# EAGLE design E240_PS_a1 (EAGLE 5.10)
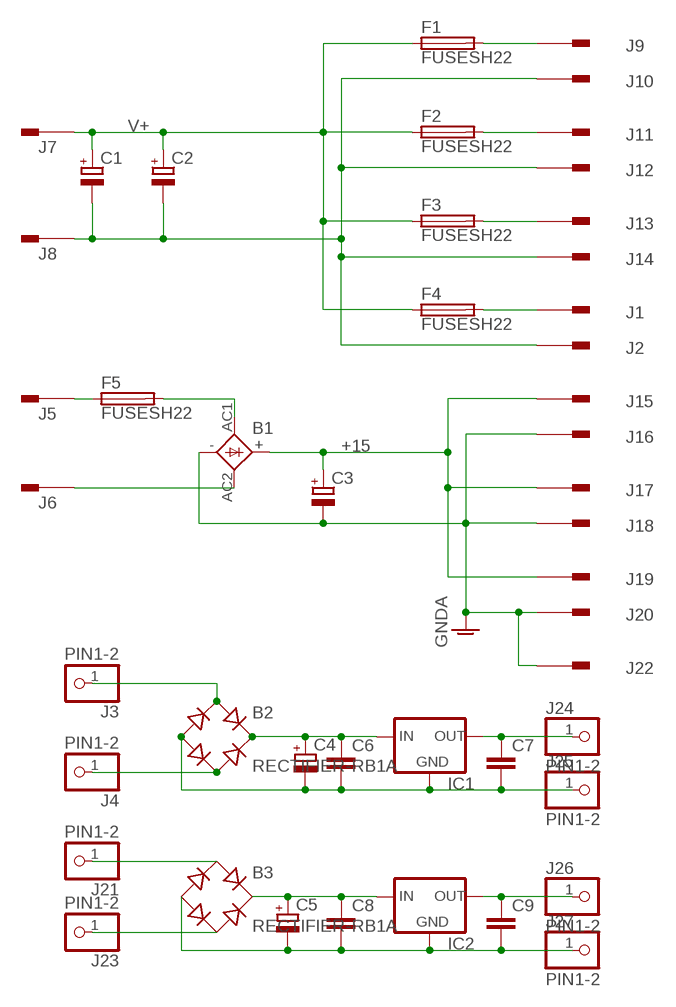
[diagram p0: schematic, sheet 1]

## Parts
B1  KBU  [KBU]
B2  RECTIFIER-RB1A  [RB1A]
B3  RECTIFIER-RB1A  [RB1A]
C1  CPOL-EUE10-35  [EB35D]
C2  CPOL-EUE10-35  [EB35D]
C3  CPOL-EUE10-22.5  [EB22,5D]
C4  CPOL-EUE5-10.5  [E5-10,5]
C5  CPOL-EUE5-10.5  [E5-10,5]
C6  C-EU050-035X075  [C050-035X075]
C7  C-EU050-035X075  [C050-035X075]
C8  C-EU050-035X075  [C050-035X075]
C9  C-EU050-035X075  [C050-035X075]
F1  FUSESH22  [SH22]
F2  FUSESH22  [SH22]
F3  FUSESH22  [SH22]
F4  FUSESH22  [SH22]
F5  FUSESH22  [SH22]
IC1  78XXS  [78XXS]
IC2  78XXS  [78XXS]
J1  PIN262409-1  [62409-1]
J2  PIN262409-1  [62409-1]
J3  PIN1-2  PINHD-1X1-RB  [1X01-B]
J4  PIN1-2  PINHD-1X1-RB  [1X01-B]
J5  PIN262409-1  [62409-1]
J6  PIN262409-1  [62409-1]
J7  PIN262409-1  [62409-1]
J8  PIN262409-1  [62409-1]
J9  PIN262409-1  [62409-1]
J10  PIN262409-1  [62409-1]
J11  PIN262409-1  [62409-1]
J12  PIN262409-1  [62409-1]
J13  PIN262409-1  [62409-1]
J14  PIN262409-1  [62409-1]
J15  PIN262409-1  [62409-1]
J16  PIN262409-1  [62409-1]
J17  PIN262409-1  [62409-1]
J18  PIN262409-1  [62409-1]
J19  PIN262409-1  [62409-1]
J20  PIN262409-1  [62409-1]
J21  PIN1-2  PINHD-1X1-RB  [1X01-B]
J22  PIN262409-1  [62409-1]
J23  PIN1-2  PINHD-1X1-RB  [1X01-B]
J24  PIN1-2  PINHD-1X1-RB  [1X01-B]
J25  PIN1-2  PINHD-1X1-RB  [1X01-B]
J26  PIN1-2  PINHD-1X1-RB  [1X01-B]
J27  PIN1-2  PINHD-1X1-RB  [1X01-B]

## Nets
+15 [PWR]: B1.+ C3.+ J15.A1 J17.A1 J19.A1
GND: B1.- C3.- J16.A1 J18.A1 J20.A1 J22.A1 ; supply symbol labelled GNDA
GNDP: C1.- C2.- J2.A1 J8.A1 J10.A1 J12.A1 J14.A1
N$1: C7.1 IC1.OUT J24.1
N$2: F1.2 J9.A1
N$3: F2.2 J11.A1
N$4 [PWR]: F5.1 J5.A1
N$5 [PWR]: B1.AC1 F5.2
N$6 [PWR]: B1.AC2 J6.A1
N$7: F3.2 J13.A1
N$8: F4.2 J1.A1
N$9: C9.1 IC2.OUT J26.1
N$10: B2.AC1 J3.1
N$11: B2.AC2 J4.1
N$12: B3.AC1 J21.1
N$13: B3.AC2 J23.1
N$14: B3.- C5.- C8.2 C9.2 IC2.GND J27.1
N$15: B3.+ C5.+ C8.1 IC2.IN
N$16: B2.- C4.- C6.2 C7.2 IC1.GND J25.1
N$17: B2.+ C4.+ C6.1 IC1.IN
V+ [PWR]: C1.+ C2.+ F1.1 F2.1 F3.1 F4.1 J7.A1
Unconnected: J1.A2(1.1) J2.A2(1.1) J5.A2(1.1) J6.A2(1.1) J7.A2(1.1) J8.A2(1.1) J9.A2(1.1) J10.A2(1.1) J11.A2(1.1) J12.A2(1.1) J13.A2(1.1) J14.A2(1.1) J15.A2(1.1) J16.A2(1.1) J17.A2(1.1) J18.A2(1.1) J19.A2(1.1) J20.A2(1.1) J22.A2(1.1)

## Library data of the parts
B1 = rectifier:KBU: DIOTEC RECTIFIER
B2 B3 = rectifier:RECTIFIER-: Rectifier
C1-C5 = rcl:CPOL-EU: POLARIZED CAPACITOR, European symbol
C6-C9 = rcl:C-EU: CAPACITOR, European symbol
F1-F5 = fuse:FUSE: Fuse
IC1 IC2 = v-reg:78XXS: VOLTAGE REGULATOR
J1 J2 J5-J20 J22 = con-faston:PIN2: Flachstecker Typ Tyco/Electronics/AMP TAB, FASTON
J3 J4 J21 J23-J27 = pinhead:PINHD-1X1: PIN HEADER

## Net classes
0 default: width 0.61 mm, clearance 0.305 mm
1 PWR: width 1.778 mm, clearance 0.305 mm
2 VCC: width 0.61 mm
4 GND: width 0.406 mm

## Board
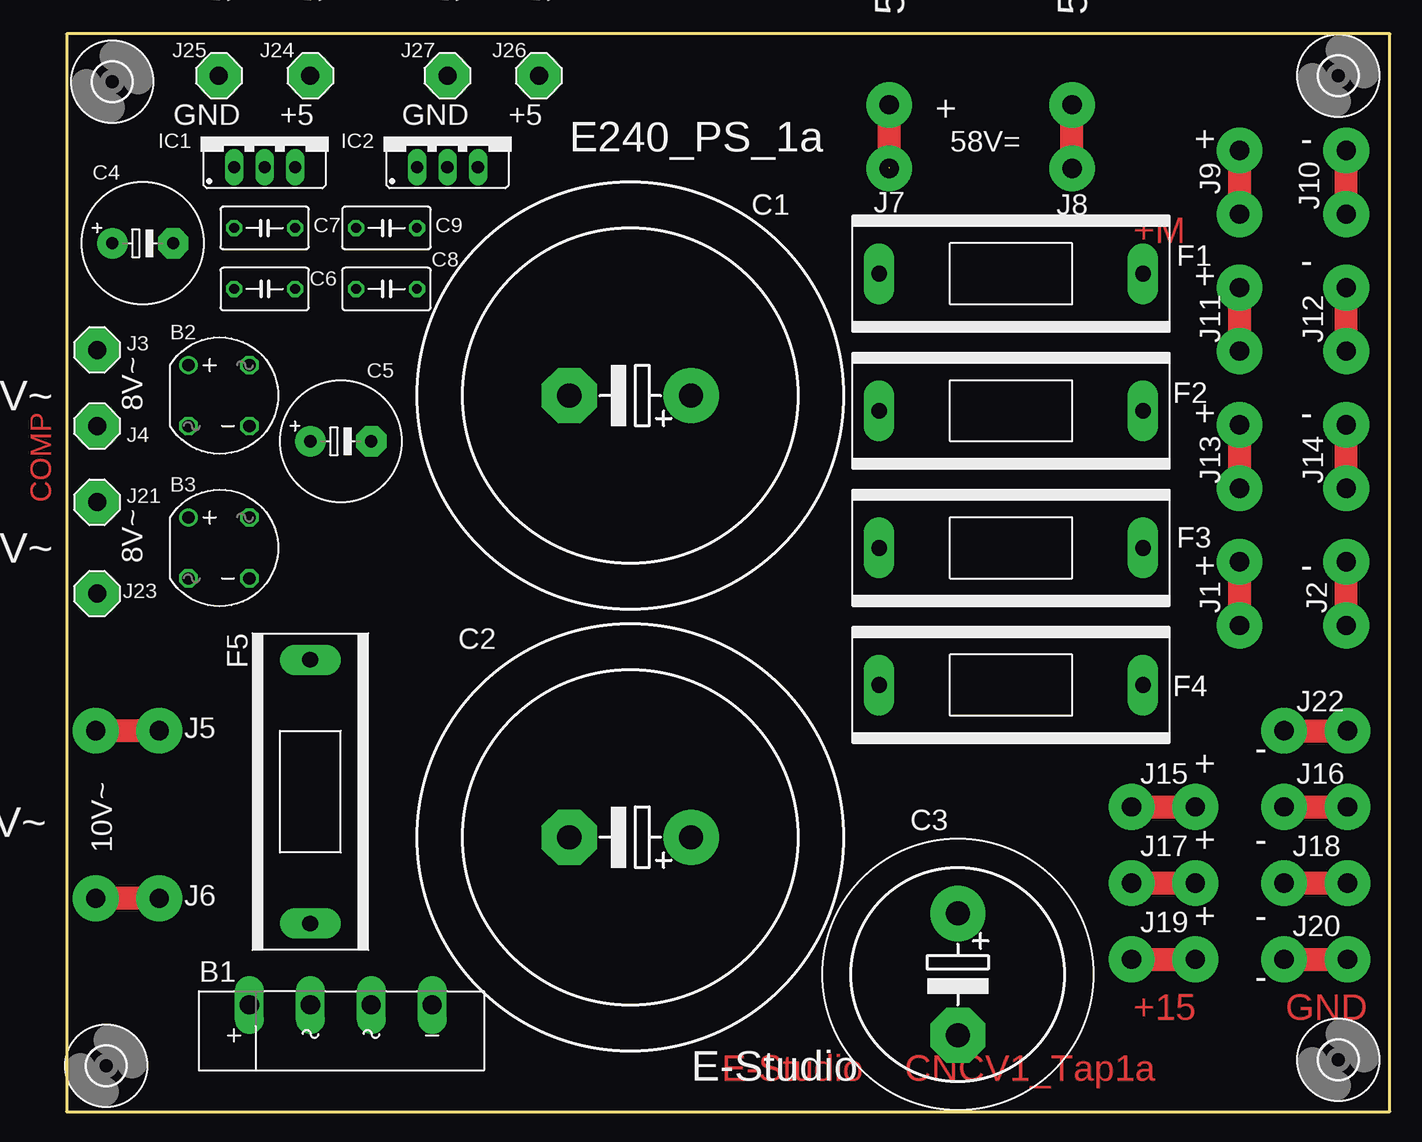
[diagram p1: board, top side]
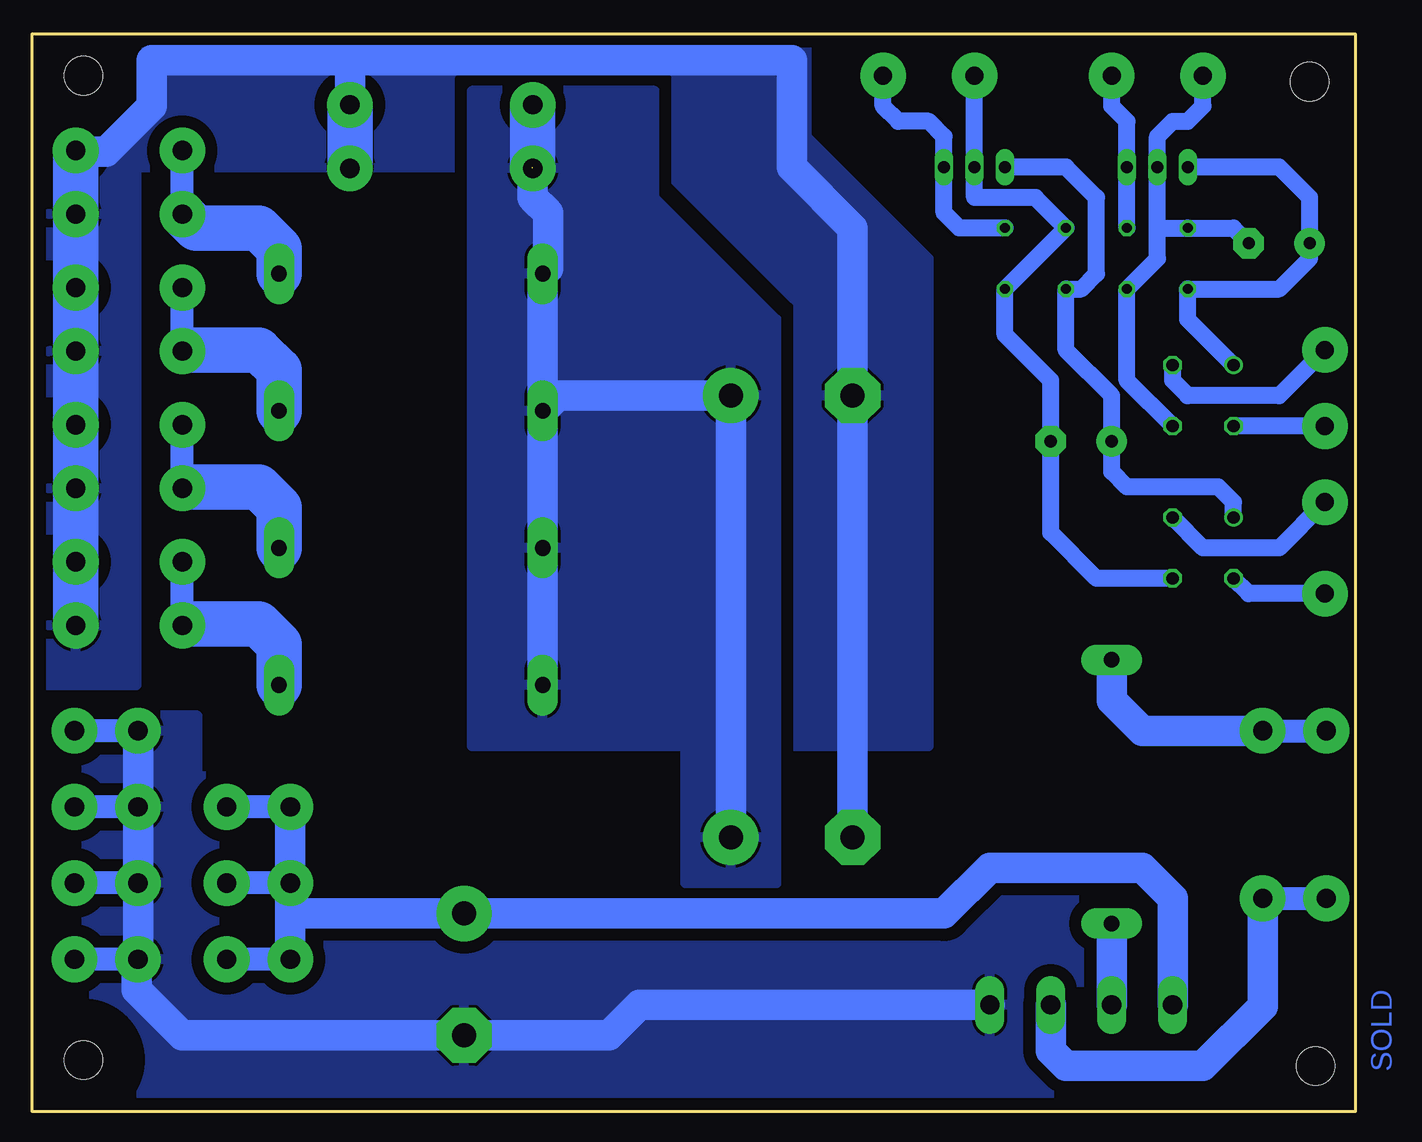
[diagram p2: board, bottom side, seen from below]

Size 110.31 x 89.84 mm. Coordinates in mm from the lower left corner, seen from the top.
Outline: 0,0 110.31,0 110.31,89.84 0,89.84 0,0
Copper layers (1*16): Top 0.035mm / dielectric 1.5mm / Bottom 0.035mm
Design rules "default": minimum track width 10mil, minimum drill 24mil, track to track 8mil, track to pad 8mil, pad to pad 8mil, via to via 8mil, smd to smd 8mil, copper to edge 40mil, drill to drill 8mil, minimum pad ring 10mil, minimum via ring 8mil, stop-mask expansion 4mil, vias tented up to drill 0mil, thermal gap 10mil

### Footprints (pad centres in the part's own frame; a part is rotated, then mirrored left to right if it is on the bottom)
KBU = drill 1.6 long: + -7.62,2.54; - 7.62,2.54; AC1 -2.54,2.54; AC2 2.54,2.54
RB1A = drill 1.016 round: + -2.54,2.54 | drill 1.016 octagon: - 2.54,-2.54; AC1 2.54,2.54; AC2 -2.54,-2.54
EB35D = drill 2.007 pad 4.597 round: + -5.08,0 | drill 2.007 pad 4.597 octagon: - 5.08,0
EB22,5D = drill 2.007 pad 4.597 round: + -5.08,0 | drill 2.007 pad 4.597 octagon: - 5.08,0
E5-10,5 = drill 1.016 pad 2.54 round: + -2.54,0 | drill 1.016 pad 2.54 octagon: - 2.54,0
C050-035X075 = drill 0.813 octagon: 1 -2.54,0; 2 2.54,0
SH22 = drill 1.321 pad 2.54 long: 1 -10.998,0; 2 10.998,0
78XXS = drill 1.016 long: GND 0,-2.54; IN -2.54,-2.54; OUT 2.54,-2.54
62409-1 = drill 1.6 pad 3.81 round: A1 -2.65,0; A2 2.65,0
1X01-B = drill 1.5 pad 3.81 round: 1 0,0
3,2 = hole 3.2: 0,0

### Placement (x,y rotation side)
B1  22.86,6.35 0 top
B2  12.7,59.69 0 top
B3  12.7,46.99 0 top
C1  46.99,59.69 180 top
C2  46.99,22.86 180 top
C3  74.3,11.43 270 top
C4  6.35,72.39 0 top
C5  22.86,55.88 0 top
C6  16.51,68.58 0 top
C7  16.51,73.66 180 top
C8  26.67,68.58 0 top
C9  26.67,73.66 180 top
F1  78.74,69.85 0 top
F2  78.74,58.42 0 top
F3  78.74,46.99 0 top
F4  78.74,35.56 0 top
F5  20.32,26.67 270 top
IC1  16.51,81.28 0 top
IC2  31.75,81.28 0 top
J1  97.79,43.18 90 top
J2  106.68,43.18 90 top
J3  2.54,63.5 0 top
J4  2.54,57.15 0 top
J5  5.08,31.75 180 top
J6  5.08,17.78 180 top
J7  68.58,81.28 90 top
J8  83.82,81.28 90 top
J9  97.79,77.47 90 top
J10  106.68,77.47 90 top
J11  97.79,66.04 90 top
J12  106.68,66.04 90 top
J13  97.79,54.61 90 top
J14  106.68,54.61 90 top
J15  91.44,25.4 0 top
J16  104.14,25.4 0 top
J17  91.44,19.05 0 top
J18  104.14,19.05 0 top
J19  91.44,12.7 0 top
J20  104.14,12.7 0 top
J21  2.54,50.8 0 top
J22  104.14,31.75 0 top
J23  2.54,43.18 0 top
J24  20.32,86.36 0 top
J25  12.7,86.36 0 top
J26  39.37,86.36 0 top
J27  31.75,86.36 0 top
U$1  [3,2]  106.02,86.36 0 top
U$2  [3,2]  106.02,4.31 0 top
U$3  [3,2]  3.31,3.81 0 top
U$4  [3,2]  3.81,85.86 0 top

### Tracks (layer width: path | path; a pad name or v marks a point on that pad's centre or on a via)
+15
  Bottom 2.54: B1.+ 15.24,17.78 17.78,20.32 30.48,20.32 34.29,16.51 C3.+ 88.79,16.51 | 88.79,16.51 J19.A1 | 88.79,16.51 J17.A1 | J17.A1 J15.A1 88.9,25.4 88.79,25.29 J17.A1
GND
  Bottom 2.54: B1.- 59.69,8.89 62.23,6.35 71.12,6.35 C3.- 97.79,6.35 101.6,10.16 101.6,12.59 J20.A1 101.6,12.7 101.49,12.81 J18.A1 J16.A1 J22.A1
  pour Bottom (isolate 1.016, rank 4): -1.27,22.86 59.69,22.86 59.69,27.94 96.52,27.94 96.52,33.02 111.76,33.02 111.76,-1.27 -1.27,-1.27
GNDP
  Bottom 2.54: 106.68,80.01 104.14,80.01 100.33,83.82 100.33,87.63 83.82,87.63 | 83.82,87.63 46.99,87.63 46.99,78.74 41.91,73.66 C1.- C2.- | 83.82,87.63 83.82,83.82 | 83.82,78.74 J8.A1
  Bottom 3.81: 106.68,80.01 J10.A1 J12.A1 J14.A1 J2.A1 | 83.82,83.82 83.82,78.74
  pour Bottom (isolate 1.016, rank 4): 45.72,91.44 111.76,91.44 111.76,35.56 101.6,35.56 101.6,36.83 101.6,78.74 59.69,78.74 59.69,77.47 59.69,30.48 35.56,30.48 35.56,71.12 45.72,81.28
N$1
  Bottom 1.422: C7.1 IC1.OUT 19.05,82.55 20.32,83.82 J24.1
N$2
  Bottom 3.81: F1.2 89.74,71.96 91.44,73.66 96.63,73.66 J9.A1
N$3
  Bottom 2.54: 97.68,63.5 J11.A1
  Bottom 3.81: F2.2 89.74,61.8 91.44,63.5 97.68,63.5
N$4
  Bottom 2.54: J5.A1 17.78,31.75 20.32,34.29 F5.1
N$5
  Bottom 2.54: B1.AC1 F5.2
N$6
  Bottom 2.54: J6.A1 7.73,8.78 12.7,3.81 24.13,3.81 25.4,5.08 B1.AC2
N$7
  Bottom 2.54: 97.68,52.07 J13.A1
  Bottom 3.81: F3.2 89.74,50.37 91.44,52.07 97.68,52.07
N$8
  Bottom 2.54: 97.68,40.64 J1.A1
  Bottom 3.81: F4.2 89.74,38.94 91.44,40.64 97.68,40.64
N$9
  Bottom 1.422: C9.1 33.02,73.66 34.29,74.93 IC2.OUT 34.29,81.28 35.56,82.55 38.1,82.55 39.37,83.82 J26.1
N$10
  Bottom 1.422: J3.1 6.35,59.69 13.97,59.69 15.24,60.96 B2.AC1
N$11
  Bottom 1.422: J4.1 B2.AC2
N$12
  Bottom 1.422: J21.1 6.35,46.99 12.7,46.99 B3.AC1
N$13
  Bottom 1.422: J23.1 8.89,43.18 B3.AC2
N$14
  Bottom 1.422: B3.- 21.59,44.45 25.4,48.26 C5.- 25.4,60.96 29.21,64.77 C8.2 C9.2 26.67,76.2 31.75,76.2 IC2.GND J27.1
N$15
  Bottom 1.422: IC2.IN 24.13,78.74 21.59,76.2 21.59,69.85 22.86,68.58 C8.1 24.13,63.5 20.32,59.69 C5.+ 20.32,53.34 19.05,52.07 11.43,52.07 10.16,50.8 B3.+
N$16
  Bottom 1.422: B2.- 19.05,60.96 C6.2 16.51,71.12 16.51,73.66 | 16.51,73.66 C7.2 10.16,73.66 C4.- | 16.51,73.66 IC1.GND 16.51,81.28 15.24,82.55 13.97,82.55 12.7,83.82 J25.1
N$17
  Bottom 1.422: B2.+ 13.97,66.04 C6.1 6.35,68.58 3.81,71.12 C4.+ 3.81,76.2 6.35,78.74 IC1.IN
V+  (1 unrouted)
  Bottom 2.54: J7.A1 68.58,76.2 67.31,74.93 67.31,70.28 F1.1 F2.1 | F2.1 F3.1 F4.1 | C2.+ C1.+ 66.47,59.69 F2.1
  Bottom 3.81: 68.58,78.74 68.58,83.82
  pour Bottom (isolate 0.813, rank 3): 48.26,19.05 48.26,66.04 58.42,76.2 58.42,85.09 73.66,85.09 73.66,30.48 55.88,30.48 55.88,19.05

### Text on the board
Top: +M | COMP | +15 | GND | E-Studio | CNCV1_Tap1a
Bottom: SOLD
tPlace: 5V GND | 5V= | 5V GND | 5V= | 58V+ | 58V GND | + | GND | +5 | GND | +5 | E240_PS_1a | 58V= | + | - | - | + | 58V= | 8V~ | 8V~ | + | - | 8V~ | 8V~ | + | - | - | + | 10V~ | 10V~ | + | - | 14V= | + | - | - | E-Studio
